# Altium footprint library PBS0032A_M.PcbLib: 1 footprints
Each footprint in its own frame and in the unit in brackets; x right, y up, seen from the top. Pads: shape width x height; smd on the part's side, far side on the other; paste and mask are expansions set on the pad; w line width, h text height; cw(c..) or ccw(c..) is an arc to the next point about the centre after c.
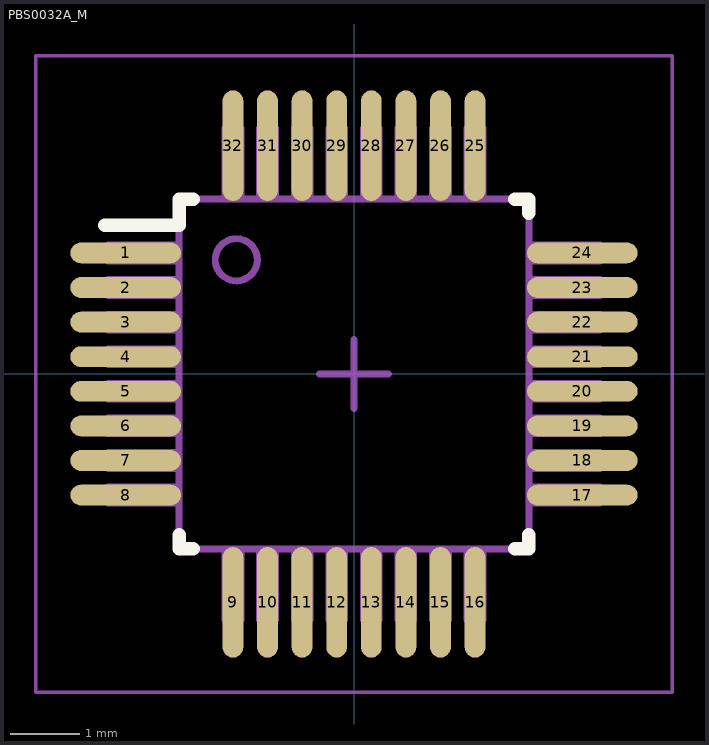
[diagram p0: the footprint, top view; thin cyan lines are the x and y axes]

## PBS0032A_M [mm]
height 1.2
pads (32):
  oval 1.6x0.3 smd: 1(-3.3,1.75) 2(-3.3,1.25) 3(-3.3,0.75) 4(-3.3,0.25) 5(-3.3,-0.25) 6(-3.3,-0.75) 7(-3.3,-1.25) 8(-3.3,-1.75) 17(3.3,-1.75) 18(3.3,-1.25) 19(3.3,-0.75) 20(3.3,-0.25) 21(3.3,0.25) 22(3.3,0.75) 23(3.3,1.25) 24(3.3,1.75)
  oval 0.3x1.6 smd: 9(-1.75,-3.3) 10(-1.25,-3.3) 11(-0.75,-3.3) 12(-0.25,-3.3) 13(0.25,-3.3) 14(0.75,-3.3) 15(1.25,-3.3) 16(1.75,-3.3) 25(1.75,3.3) 26(1.25,3.3) 27(0.75,3.3) 28(0.25,3.3) 29(-0.25,3.3) 30(-0.75,3.3) 31(-1.25,3.3) 32(-1.75,3.3)
Top Overlay:
  lines w0.2: -3.6,2.15 -2.527,2.15 -2.527,2.527 -2.327,2.527 ; -2.527,-2.327 -2.527,-2.527 -2.327,-2.527 ; 2.327,-2.527 2.527,-2.527 2.527,-2.327 ; 2.327,2.527 2.527,2.527 2.527,2.327
Mechanical 5:
  circle w0.1: c-1.702,1.651 r0.305
  lines w0.1: -3.556,-1.864 -2.527,-1.864 -2.527,-1.636 -3.556,-1.636 -3.556,-1.864 ; -3.556,-1.364 -2.527,-1.364 -2.527,-1.136 -3.556,-1.136 -3.556,-1.364 ; -3.556,-0.864 -2.527,-0.864 -2.527,-0.636 -3.556,-0.636 -3.556,-0.864 ; -3.556,-0.364 -2.527,-0.364 -2.527,-0.136 -3.556,-0.136 -3.556,-0.364 ; -3.556,0.136 -2.527,0.136 -2.527,0.364 -3.556,0.364 -3.556,0.136 ; -3.556,0.636 -2.527,0.636 -2.527,0.864 -3.556,0.864 -3.556,0.636 ; -3.556,1.136 -2.527,1.136 -2.527,1.364 -3.556,1.364 -3.556,1.136 ; -3.556,1.636 -2.527,1.636 -2.527,1.864 -3.556,1.864 -3.556,1.636 ; -2.527,-2.527 -2.527,2.527 2.527,2.527 2.527,-2.527 -2.527,-2.527 ; -1.864,-3.556 -1.636,-3.556 -1.636,-2.527 -1.864,-2.527 -1.864,-3.556 ; -1.864,2.527 -1.864,3.556 -1.636,3.556 -1.636,2.527 -1.864,2.527 ; -1.364,-3.556 -1.136,-3.556 -1.136,-2.527 -1.364,-2.527 -1.364,-3.556 ; -1.364,2.527 -1.364,3.556 -1.136,3.556 -1.136,2.527 -1.364,2.527 ; -0.864,-3.556 -0.636,-3.556 -0.636,-2.527 -0.864,-2.527 -0.864,-3.556 ; -0.864,2.527 -0.864,3.556 -0.636,3.556 -0.636,2.527 -0.864,2.527 ; -0.364,-3.556 -0.136,-3.556 -0.136,-2.527 -0.364,-2.527 -0.364,-3.556 ; -0.364,2.527 -0.364,3.556 -0.136,3.556 -0.136,2.527 -0.364,2.527 ; 0.136,-3.556 0.364,-3.556 0.364,-2.527 0.136,-2.527 0.136,-3.556 ; 0.136,2.527 0.136,3.556 0.364,3.556 0.364,2.527 0.136,2.527 ; 0.636,-3.556 0.864,-3.556 0.864,-2.527 0.636,-2.527 0.636,-3.556 ; 0.636,2.527 0.636,3.556 0.864,3.556 0.864,2.527 0.636,2.527 ; 1.136,-3.556 1.364,-3.556 1.364,-2.527 1.136,-2.527 1.136,-3.556 ; 1.136,2.527 1.136,3.556 1.364,3.556 1.364,2.527 1.136,2.527 ; 1.636,-3.556 1.864,-3.556 1.864,-2.527 1.636,-2.527 1.636,-3.556 ; 1.636,2.527 1.636,3.556 1.864,3.556 1.864,2.527 1.636,2.527 ; 2.527,-1.864 3.556,-1.864 3.556,-1.636 2.527,-1.636 2.527,-1.864 ; 2.527,-1.364 3.556,-1.364 3.556,-1.136 2.527,-1.136 2.527,-1.364 ; 2.527,-0.864 3.556,-0.864 3.556,-0.636 2.527,-0.636 2.527,-0.864 ; 2.527,-0.364 3.556,-0.364 3.556,-0.136 2.527,-0.136 2.527,-0.364 ; 2.527,0.136 3.556,0.136 3.556,0.364 2.527,0.364 2.527,0.136 ; 2.527,0.636 3.556,0.636 3.556,0.864 2.527,0.864 2.527,0.636 ; 2.527,1.136 3.556,1.136 3.556,1.364 2.527,1.364 2.527,1.136 ; 2.527,1.636 3.556,1.636 3.556,1.864 2.527,1.864 2.527,1.636
  text ".Designator" at -2.03,-0.63 h1.1
Mechanical 15:
  lines w0.05: -4.6,-4.6 4.6,-4.6 4.6,4.6 -4.6,4.6 -4.6,-4.6
  lines w0.1: -0.5,0 0.5,0 ; 0,-0.5 0,0.5
3D body: height 1.2, standoff 0, extent -3.505,-3.505 3.506,3.506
